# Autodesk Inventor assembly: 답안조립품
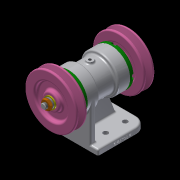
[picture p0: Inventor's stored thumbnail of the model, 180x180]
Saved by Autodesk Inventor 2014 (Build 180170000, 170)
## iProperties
Created: 2020-06
Part Number: 답안조립품
Document SubType Name: Assembly
Designer: kh
Author: kh
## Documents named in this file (12)
- C:\Users\kh\Desktop\700606V1054\답안조립품.iam
- C:\Users\kh\Desktop\700606V1054\본체.ipt
- C:\Users\kh\Desktop\700606V1054\Ű 5x5x12.ipt
- C:\Users\kh\Desktop\700606V1054\V-벨트풀리.ipt
- C:\Users\kh\Desktop\700606V1054\너트 M10.ipt
- C:\Users\kh\Desktop\700606V1054\베어링 6204.ipt
- C:\Users\kh\Desktop\700606V1054\볼트 M4.ipt
- C:\Users\kh\Desktop\700606V1054\스프링 와셔 10.ipt
- C:\Users\kh\Desktop\700606V1054\오일 실 20 32 5.ipt
- C:\Users\kh\Desktop\700606V1054\축.ipt
- C:\Users\kh\Desktop\700606V1054\커버.ipt
- C:\Users\kh\Desktop\700606V1054\평면 와셔 10x21.ipt
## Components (4 placed, 2 different names)
1. Ű 5x5x12:1 — Mate:1, Mate:2, Mate:3, Mate:7
2. V-벨트풀리:1 — Mate:7, Mate:8, Mate:9, Mate:10
3. Ű 5x5x12:2 — Mate:4, Mate:5, Mate:6, Mate:17
4. V-벨트풀리:2 — Mate:16, Mate:17, Mate:18, Mate:19
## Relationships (14: Mate 14)
- Mate:1: Ű 5x5x12:1
- Mate:2: Ű 5x5x12:1
- Mate:3: Ű 5x5x12:1
- Mate:4: Ű 5x5x12:2
- Mate:5: Ű 5x5x12:2
- Mate:6: Ű 5x5x12:2
- Mate:7: Ű 5x5x12:1 ↔ V-벨트풀리:1
- Mate:8: V-벨트풀리:1
- Mate:9: V-벨트풀리:1
- Mate:10: V-벨트풀리:1
- Mate:16: V-벨트풀리:2
- Mate:17: Ű 5x5x12:2 ↔ V-벨트풀리:2
- Mate:18: V-벨트풀리:2
- Mate:19: V-벨트풀리:2
